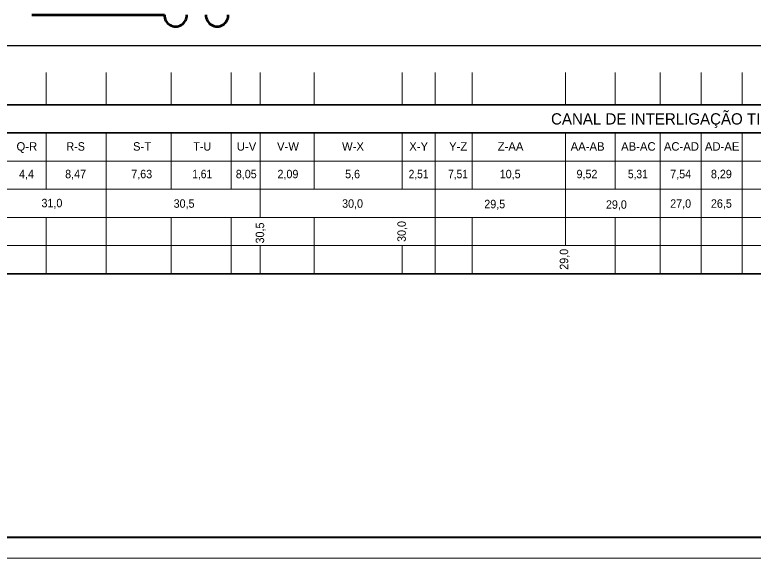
# Model space of a CAD drawing. Extents: x 8458 to 9360, y 19921 to 20366.
# Drawn here: x 8766.6 to 9028.9, y 19920.7 to 20113.5 of the extents above; entities that cross this region are included whole.
import ezdxf

# ---------------------------------------------------------------- set-up
doc = ezdxf.new("R2010")
doc.units = 0
doc.header["$LTSCALE"] = 1.2
doc.layers.add('1', color=7, linetype='Continuous', lineweight=40)
doc.layers.add('5', color=7, linetype='Continuous', lineweight=13)

msp = doc.modelspace()

# ---------------------------------------------------------------- linework, layer by layer
at = {"layer": '1'}
msp.add_line((8495.27, 19928.17), (9352.57, 19928.17), dxfattribs=at)
at = {"layer": '1', "lineweight": 13}
msp.add_lwpolyline([(8457.77, 19920.67), (9360.07, 19920.67), (9360.07, 20366.17), (8457.77, 20366.17)], close=True, dxfattribs=at)
at = {"layer": '5', "lineweight": 53}
msp.add_line((8772.65, 20113.48), (8819.76, 20113.48), dxfattribs=at)
at = {"layer": '5', "lineweight": 25}
msp.add_line((8509.89, 20102.58), (9341.84, 20102.58), dxfattribs=at)
at = {"layer": '5'}
for p, q in [((8777.75, 20093.05), (8777.75, 20081.6)), ((8799.1, 20093.05), (8799.1, 20081.6)), ((8822.2, 20093.05), (8822.2, 20081.6)), ((8843.46, 20093.05), (8843.46, 20081.6)), ((8853.81, 20093.05), (8853.81, 20081.6)), ((8872.98, 20093.05), (8872.98, 20081.6)), ((8904.22, 20093.05), (8904.22, 20081.6)), ((8915.91, 20093.05), (8915.91, 20081.6)), ((8929.07, 20093.05), (8929.07, 20081.6)), ((8962.14, 20093.05), (8962.14, 20081.6)), ((8979.8, 20093.05), (8979.8, 20081.6)), ((8995.81, 20093.05), (8995.81, 20081.6)), ((9010.39, 20093.05), (9010.39, 20081.6)), ((9024.97, 20093.05), (9024.97, 20081.61)), ((8777.75, 20071.6), (8777.75, 20051.6)), ((8799.1, 20071.6), (8799.1, 20021.6)), ((8822.2, 20071.6), (8822.2, 20051.6)), ((8843.46, 20071.6), (8843.46, 20051.6)), ((8853.81, 20071.6), (8853.81, 20041.6)), ((8872.98, 20071.6), (8872.98, 20051.6)), ((8904.22, 20071.6), (8904.22, 20051.6)), ((8915.91, 20071.6), (8915.91, 20021.6)), ((8929.07, 20071.6), (8929.07, 20051.6)), ((8962.14, 20071.6), (8962.14, 20031.6)), ((8979.8, 20071.6), (8979.8, 20051.6)), ((8995.81, 20071.6), (8995.81, 20021.6)), ((9010.39, 20071.6), (9010.39, 20021.6)), ((9024.97, 20071.61), (9024.97, 20021.61)), ((8517.12, 20061.6), (9319.97, 20061.61)), ((8517.12, 20051.6), (9319.97, 20051.61)), ((8517.12, 20041.6), (9319.97, 20041.61)), ((8535.69, 20041.6), (9319.97, 20041.61)), ((8777.75, 20041.6), (8777.75, 20021.6)), ((8822.2, 20041.6), (8822.2, 20021.6)), ((8843.46, 20041.6), (8843.46, 20021.6)), ((8872.98, 20041.6), (8872.98, 20021.6)), ((8929.07, 20041.6), (8929.07, 20021.6)), ((8979.8, 20041.6), (8979.8, 20021.6)), ((8517.12, 20031.6), (9319.97, 20031.61)), ((8853.81, 20031.6), (8853.81, 20021.6)), ((8904.22, 20031.6), (8904.22, 20021.6))]:
    msp.add_line(p, q, dxfattribs=at)
at = {"layer": '5', "lineweight": 35}
for p, q in [((8585.69, 20081.6), (9319.97, 20081.61)), ((8585.69, 20071.6), (9319.97, 20071.61)), ((8517.12, 20021.6), (9319.97, 20021.61))]:
    msp.add_line(p, q, dxfattribs=at)
at = {"layer": '5', "lineweight": 53}
for centre in [(8823.73, 20113.35), (8838.48, 20113.35)]:
    msp.add_arc(centre, 3.97, 178.3116, 2.5541, dxfattribs=at)

# ---------------------------------------------------------------- texts
at = {"layer": '5'}
for s, height, p in [('CANAL DE INTERLIGAÇÃO TIPO CANAL/DIQUE', 4, (8957.07, 20074.59)), ('Q-R', 3, (8767.24, 20065.32)), ('S-T', 3, (8808.6, 20065.32)), ('U-V', 3, (8845.47, 20065.32)), ('V-W', 3, (8859.75, 20065.32)), ('W-X', 3, (8882.83, 20065.32)), ('X-Y', 3, (8906.71, 20065.32)), ('Y-Z', 3, (8920.86, 20065.32)), ('Z-AA', 3, (8938.12, 20065.32)), ('AA-AB', 3, (8964.03, 20065.32)), ('AB-AC', 3, (8981.94, 20065.32)), ('AC-AD', 3, (8997.12, 20065.32)), ('AD-AE', 3, (9011.69, 20065.32))]:
    msp.add_text(s, height=height, dxfattribs=at).set_placement(p)
for s, width, p in [('R-S', 0.95, (8784.96, 20065.32)), ('T-U', 0.95, (8830.02, 20065.32)), ('4,4', 0.95, (8768.14, 20055.52)), ('8,47', 0.95, (8784.52, 20055.52)), ('7,63', 0.95, (8808, 20055.52)), ('1,61', 0.9, (8829.66, 20055.52)), ('8,05', 0.95, (8845.12, 20055.52)), ('2,09', 0.95, (8859.92, 20055.52)), ('5,6', 0.95, (8883.94, 20055.52)), ('2,51', 0.9, (8906.5, 20055.52)), ('7,51', 0.9, (8920.51, 20055.52)), ('10,5', 0.95, (8938.84, 20055.52)), ('9,52', 0.95, (8966.11, 20055.52)), ('5,31', 0.9, (8984.37, 20055.52)), ('7,54', 0.95, (8999.38, 20055.52)), ('8,29', 0.95, (9013.84, 20055.52)), ('31,0', 0.95, (8776.11, 20045.22)), ('30,5', 0.95, (8823.04, 20045.05)), ('30,0', 0.95, (8882.86, 20045.05)), ('29,5', 0.95, (8933.36, 20044.87)), ('27,0', 0.95, (8999.38, 20045.05)), ('26,5', 0.95, (9013.84, 20045.05)), ('29,0', 0.95, (8976.56, 20044.7))]:
    msp.add_text(s, height=3, dxfattribs=dict(at, width=width)).set_placement(p)
at = {"layer": '5', "width": 0.95}
for s, p in [('30,0', (8905.49, 20032.92)), ('30,5', (8855.18, 20032.38)), ('29,0', (8963.15, 20023.05))]:
    msp.add_text(s, height=3, rotation=90, dxfattribs=at).set_placement(p)

doc.saveas('drawing.dxf')
